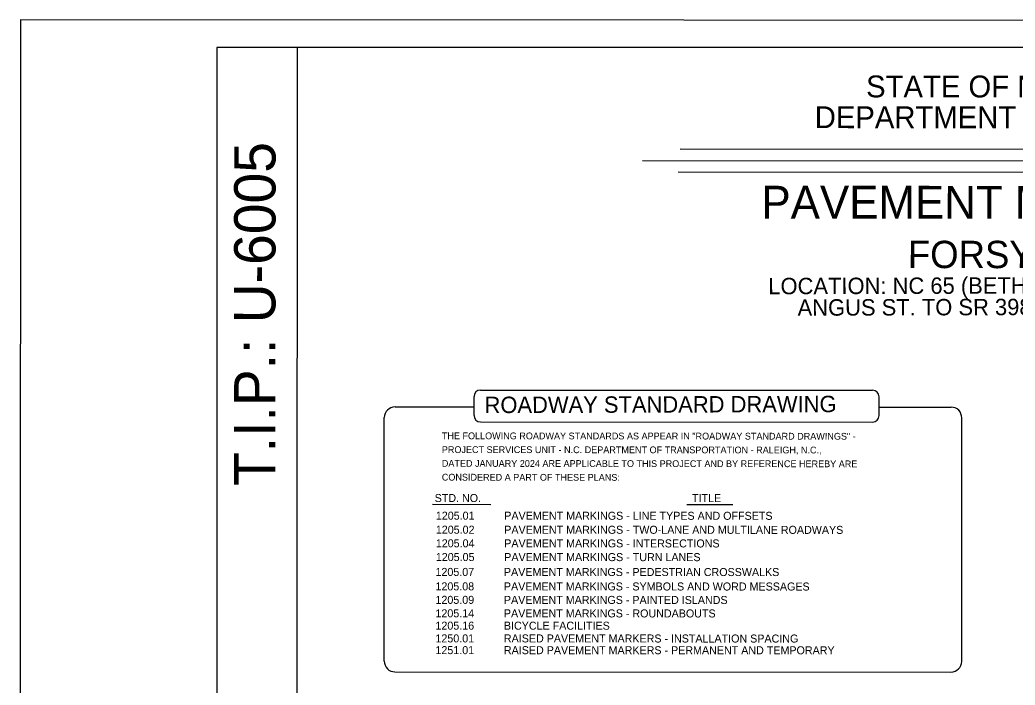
# Model space of a CAD drawing. Extents: x 50667 to 52386, y 46650 to 50479.
# Drawn here: x 50703 to 51544, y 49917 to 50479 of the extents above; entities that cross this region are included whole.
import ezdxf

# ---------------------------------------------------------------- set-up
doc = ezdxf.new("R2010")
doc.units = 0
for name, color, linetype in [('Default', 7, 'Continuous'), ('DEV TUBULAR MARKER SECTIONAL VIEW CELL', 7, 'Continuous'), ('Exist Utilities Power Pole Text Tag Number', 7, 'Continuous'), ('Old_Level_51', 7, 'Continuous'), ('TSCONFLICT', 7, 'Continuous')]:
    doc.layers.add(name, color=color, linetype=linetype)

msp = doc.modelspace()

# ---------------------------------------------------------------- linework, layer by layer
at = {"layer": 'Default'}
for points in [[(51261.15, 50370.27), (51954.95, 50369.95)], [(51229.19, 50360.53), (51983.6, 50360.18)], [(51259.46, 50350.77), (51953.26, 50350.44)]]:
    msp.add_lwpolyline(points, dxfattribs=at)
at = {"layer": 'DEV TUBULAR MARKER SECTIONAL VIEW CELL'}
msp.add_lwpolyline([(52369.04, 50455.98), (50869.05, 50455.87), (50869.12, 49405.87), (52369.12, 49405.98)], close=True, dxfattribs=at)
at = {"layer": 'Exist Utilities Power Pole Text Tag Number'}
msp.add_lwpolyline([(52386.04, 50478.48), (50703.13, 50479.27), (50702.62, 49383.36), (52385.53, 49382.58)], close=True, dxfattribs=at)
at = {"layer": 'TSCONFLICT'}
for p, q in [((51086.71, 50144.92), (51086.72, 50160.95)), ((51429.26, 50144.76), (51429.27, 50160.79)), ((51019.92, 50152.17), (51086.72, 50152.14)), ((51429.26, 50151.98), (51490.2, 50151.95)), ((51010.73, 49937.31), (51010.83, 50143.09)), ((51499.19, 49937.09), (51499.29, 50142.86)), ((51051.58, 50069.82), (51100.83, 50069.79)), ((51266.8, 50069.72), (51305.64, 50069.7)), ((51019.82, 49928.22), (51490.1, 49928))]:
    msp.add_line(p, q, dxfattribs=at)
for points in [[(50936.87, 49405.88), (50937.36, 50455.88)], [(51092.18, 50166.4), (51423.82, 50166.24)], [(51092.16, 50139.47), (51423.8, 50139.31)]]:
    msp.add_lwpolyline(points, dxfattribs=at)
for centre, radius, start, end in [((51092.17, 50160.94), 5.45, 89.97341, 179.97341), ((51423.81, 50160.79), 5.45, 359.97341, 89.97341), ((51019.92, 50143.08), 9.09, 89.97341, 179.97341), ((51490.2, 50142.87), 9.09, 359.97341, 89.97341), ((51092.17, 50144.92), 5.45, 179.97341, 269.97341), ((51423.81, 50144.77), 5.45, 269.97341, 359.97341), ((51019.82, 49937.31), 9.09, 179.97341, 269.97341), ((51490.1, 49937.09), 9.09, 269.97341, 359.97341)]:
    msp.add_arc(centre, radius, start, end, dxfattribs=at)

# ---------------------------------------------------------------- texts
at = {"layer": 'Default'}
for s, height, rotation, p in [('STATE OF NORTH CAROLINA', 18.4936, 359.97341, (51418.32, 50413.79)), ('DEPARTMENT OF TRANSPORTATION', 18.4936, 359.97341, (51374.88, 50387.78)), ('T.I.P.: U-6005', 34.925, 89.97341, (50918.68, 50085.33)), ('PAVEMENT MARKING PLAN', 27.7403, 359.97341, (51329.78, 50311.35)), ('FORSYTH COUNTY', 23.1165, 359.97341, (51453.61, 50269.48)), ('LOCATION: NC 65 (BETHANIA RURAL HALL RD.) FROM', 13.8702, 0.15565, (51335.63, 50247.33)), ('ANGUS ST. TO SR 3983 (NORTHRIDGE PARK DR.)', 13.8702, 0.15565, (51360.38, 50229.21)), ('ROADWAY STANDARD DRAWING', 13.8661, 0.15565, (51095.62, 50146.91)), ('STD. NO.', 6.771, 359.97341, (51053.42, 50071.78)), ('TITLE', 6.771, 359.97341, (51271.08, 50071.67)), ('1205.01          PAVEMENT MARKINGS - LINE TYPES AND OFFSETS', 6.7709, 359.97341, (51054.41, 50056.85)), ('1205.02          PAVEMENT MARKINGS - TWO-LANE AND MULTILANE ROADWAYS', 6.7709, 359.97341, (51054.4, 50045)), ('1205.04          PAVEMENT MARKINGS - INTERSECTIONS', 6.7709, 359.97341, (51054.39, 50033.48)), ('1205.05          PAVEMENT MARKINGS - TURN LANES', 6.7709, 359.97341, (51054.39, 50021.89)), ('1205.07          PAVEMENT MARKINGS - PEDESTRIAN CROSSWALKS', 6.7709, 359.97341, (51054.11, 50009.3)), ('1205.08          PAVEMENT MARKINGS - SYMBOLS AND WORD MESSAGES', 6.7709, 359.97341, (51054.1, 49997.1)), ('1205.09          PAVEMENT MARKINGS - PAINTED ISLANDS', 6.7709, 359.97341, (51054.1, 49985.7)), ('1205.14          PAVEMENT MARKINGS - ROUNDABOUTS', 6.7709, 359.97341, (51054.09, 49974.31)), ('1205.16          BICYCLE FACILITIES', 6.7709, 359.97341, (51054.09, 49963.9)), ('1250.01          RAISED PAVEMENT MARKERS - INSTALLATION SPACING', 6.7709, 359.97341, (51054.08, 49953.12)), ('1251.01          RAISED PAVEMENT MARKERS - PERMANENT AND TEMPORARY', 6.7709, 359.97341, (51054.08, 49943.19))]:
    msp.add_text(s, height=height, rotation=rotation, dxfattribs=at).set_placement(p)
at = {"layer": 'Old_Level_51'}
for s, p in [('THE FOLLOWING ROADWAY STANDARDS AS APPEAR IN "ROADWAY STANDARD DRAWINGS" -', (51059.5, 50124.87)), ('PROJECT SERVICES UNIT - N.C. DEPARTMENT OF TRANSPORTATION - RALEIGH, N.C.,', (51059.48, 50113.21)), ('DATED JANUARY 2024 ARE APPLICABLE TO THIS PROJECT AND BY REFERENCE HEREBY ARE ', (51059.47, 50101.56)), ('CONSIDERED A PART OF THESE PLANS:', (51059.46, 50089.9))]:
    msp.add_text(s, height=5.7256, rotation=359.93321, dxfattribs=at).set_placement(p)

doc.saveas('drawing.dxf')
